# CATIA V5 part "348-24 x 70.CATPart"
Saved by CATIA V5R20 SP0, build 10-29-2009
Part number: 348-24 x 70
Definition: NONE
Nomenclature: 348-24 x 70
Source: Unknown
Description: 348-24 x 70
Bounding box of the stored display mesh (mm): x 0 to 70, y -18 to 18, z -18 to 18
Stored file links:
  C:\Users\Utente\Desktop\IO LAVORO\3D X SITO CF\X SITO\3D files 348\348-24 x 70.CATPart
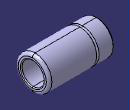
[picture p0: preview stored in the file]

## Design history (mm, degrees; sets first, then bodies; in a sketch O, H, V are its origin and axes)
Body1 "348-24 x 70" (main body)
  Solid1: solid without history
